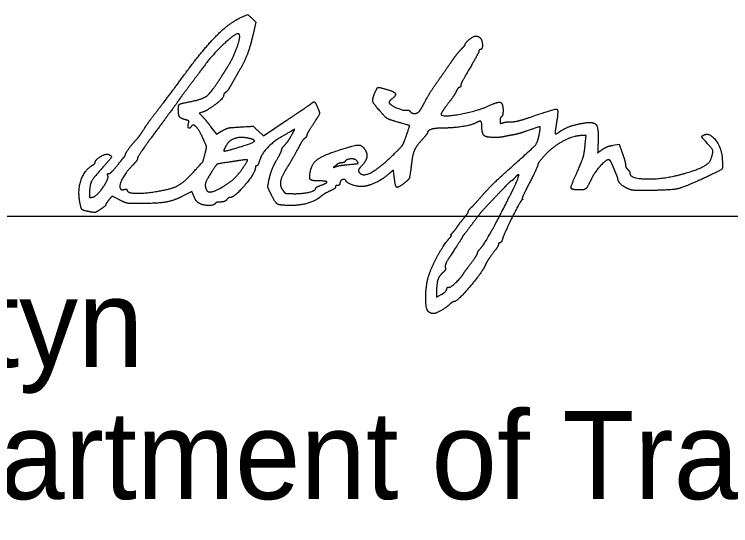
# Model space of a CAD drawing. Extents: x 0 to 34, y 0 to 22.
# Drawn here: x 25.627 to 26.765, y 7.199 to 8.012 of the extents above; entities that cross this region are included whole.
import ezdxf

# ---------------------------------------------------------------- set-up
doc = ezdxf.new("R2010")
doc.units = 0
doc.layers.add('SH_Data', color=7, linetype='Continuous')
doc.layers.add('SH_Text', color=7, linetype='Continuous')

msp = doc.modelspace()

# ---------------------------------------------------------------- linework, layer by layer
at = {"layer": 'SH_Data'}
msp.add_line((24.5, 7.691), (28, 7.691), dxfattribs=at)
at = {"layer": 'SH_Text'}
for points in [[(25.9853, 8.0062), (25.9979, 8.012), (26.0042, 8.0057), (26.0106, 7.9993), (26.0062, 7.9806)], [(25.9253, 7.8562), (25.9203, 7.8546), (25.9255, 7.8495)], [(25.9392, 7.8328), (25.9477, 7.8213), (25.9565, 7.8265)], [(26.0143, 7.8265), (26.0224, 7.8189), (26.0587, 7.843)], [(26.0682, 7.8212), (26.0726, 7.8292), (26.0671, 7.8263)], [(26.534, 7.8053), (26.5355, 7.8191), (26.5277, 7.8191)], [(26.5779, 7.8037), (26.5876, 7.8053), (26.5926, 7.7917)], [(26.23, 7.7576), (26.2293, 7.7644), (26.2234, 7.7593)], [(25.9123, 7.722), (25.909, 7.73), (25.8951, 7.7231)], [(25.7937, 7.7169), (25.7822, 7.7227), (25.7771, 7.7169)], [(26.2977, 7.5714), (26.2977, 7.5621), (26.3052, 7.5664)]]:
    msp.add_lwpolyline(points, dxfattribs=at)
for points in [[(25.8957, 7.9143), (25.9254, 7.9549), (25.9672, 7.9978), (25.9853, 8.0062)], [(25.9838, 7.9804), (25.9802, 7.984), (25.9416, 7.9483), (25.9262, 7.927)], [(25.9655, 7.9283), (25.9749, 7.9432), (25.9869, 7.9773), (25.9838, 7.9804)], [(26.0062, 7.9806), (26.0012, 7.9595), (25.992, 7.9359), (25.9826, 7.9199)], [(26.3433, 7.9643), (26.3433, 7.9671), (26.3565, 7.9774), (26.3602, 7.9775)], [(26.3602, 7.9775), (26.3623, 7.9775), (26.3652, 7.9762), (26.3668, 7.9747)], [(26.3668, 7.9747), (26.3703, 7.9712), (26.3707, 7.9559), (26.3673, 7.9559)], [(26.3367, 7.9562), (26.3403, 7.9598), (26.3433, 7.9634), (26.3433, 7.9643)], [(26.3229, 7.9389), (26.3269, 7.9448), (26.3331, 7.9525), (26.3367, 7.9562)], [(26.3649, 7.9534), (26.3649, 7.952), (26.3584, 7.9399), (26.3505, 7.9266)], [(26.3673, 7.9559), (26.366, 7.9559), (26.3649, 7.9548), (26.3649, 7.9534)], [(26.3013, 7.9079), (26.3092, 7.9192), (26.319, 7.9331), (26.3229, 7.9389)], [(25.9262, 7.927), (25.9226, 7.9221), (25.9132, 7.9094), (25.9053, 7.8989)], [(25.955, 7.9117), (25.9583, 7.9169), (25.963, 7.9244), (25.9655, 7.9283)], [(26.3505, 7.9266), (26.3426, 7.9132), (26.3361, 7.9008), (26.3361, 7.8991)], [(25.8555, 7.8609), (25.8644, 7.8722), (25.8825, 7.8963), (25.8957, 7.9143)], [(25.9052, 7.873), (25.9258, 7.8768), (25.9398, 7.8877), (25.955, 7.9117)], [(25.9826, 7.9199), (25.9791, 7.914), (25.9739, 7.9048), (25.971, 7.8995)], [(26.2799, 7.8743), (26.2837, 7.8816), (26.2933, 7.8967), (26.3013, 7.9079)], [(25.9053, 7.8989), (25.8974, 7.8884), (25.8893, 7.8774), (25.8873, 7.8745)], [(25.971, 7.8995), (25.9682, 7.8943), (25.9644, 7.8891), (25.9626, 7.888)], [(26.1992, 7.8862), (26.203, 7.8952), (26.2061, 7.8963), (26.2188, 7.8925)], [(26.2188, 7.8925), (26.2308, 7.889), (26.2337, 7.8828), (26.226, 7.8769)], [(26.3288, 7.8893), (26.3271, 7.8857), (26.3209, 7.8766), (26.3152, 7.8691)], [(26.3341, 7.8959), (26.333, 7.8959), (26.3306, 7.893), (26.3288, 7.8893)], [(26.3361, 7.8991), (26.3361, 7.8973), (26.3352, 7.8959), (26.3341, 7.8959)], [(25.9593, 7.8826), (25.9593, 7.8788), (25.9335, 7.8588), (25.9253, 7.8562)], [(25.9626, 7.888), (25.9608, 7.887), (25.9593, 7.8845), (25.9593, 7.8826)], [(26.209, 7.8568), (26.1975, 7.8698), (26.1953, 7.8766), (26.1992, 7.8862)], [(25.8873, 7.8745), (25.8853, 7.8715), (25.87, 7.8506), (25.8532, 7.8279)], [(25.8873, 7.8609), (25.8873, 7.8677), (25.8914, 7.8705), (25.9052, 7.873)], [(26.0587, 7.843), (26.0786, 7.8563), (26.0962, 7.8682), (26.0978, 7.8695)], [(26.0978, 7.8695), (26.1023, 7.8733), (26.1047, 7.8724), (26.1077, 7.8658)], [(26.226, 7.8769), (26.2233, 7.8749), (26.2218, 7.872), (26.2228, 7.8707)], [(26.2228, 7.8707), (26.2254, 7.8669), (26.2453, 7.8587), (26.25, 7.8595)], [(26.2706, 7.8581), (26.2719, 7.8598), (26.2761, 7.8671), (26.2799, 7.8743)], [(26.3152, 7.8691), (26.3096, 7.8617), (26.3049, 7.8544), (26.3049, 7.8531)], [(26.3049, 7.8531), (26.3049, 7.8478), (26.3645, 7.8587), (26.3825, 7.8673)], [(26.3825, 7.8673), (26.3955, 7.8735), (26.4033, 7.8703), (26.4033, 7.8589)], [(25.834, 7.8315), (25.837, 7.8363), (25.8467, 7.8495), (25.8555, 7.8609)], [(25.8983, 7.8445), (25.8911, 7.8463), (25.8873, 7.852), (25.8873, 7.8609)], [(26.1077, 7.8658), (26.1121, 7.8562), (26.1111, 7.8521), (26.1009, 7.8362)], [(26.2325, 7.8416), (26.2217, 7.8447), (26.2168, 7.8479), (26.209, 7.8568)], [(26.25, 7.8595), (26.2522, 7.8599), (26.2548, 7.859), (26.2556, 7.8577)], [(26.2556, 7.8577), (26.2578, 7.8542), (26.2678, 7.8545), (26.2706, 7.8581)], [(26.4033, 7.8589), (26.4033, 7.8544), (26.4022, 7.85), (26.4009, 7.8491)], [(26.4456, 7.8482), (26.486, 7.8621), (26.4919, 7.8605), (26.4878, 7.8366)], [(25.9034, 7.8382), (25.9043, 7.8418), (25.9031, 7.8433), (25.8983, 7.8445)], [(25.9255, 7.8495), (25.9283, 7.8467), (25.9345, 7.8392), (25.9392, 7.8328)], [(26.4009, 7.8491), (26.3996, 7.8483), (26.3985, 7.8455), (26.3985, 7.8428)], [(26.4168, 7.8412), (26.421, 7.841), (26.4339, 7.8442), (26.4456, 7.8482)], [(25.9077, 7.8335), (25.9052, 7.8296), (25.902, 7.8331), (25.9034, 7.8382)], [(25.9265, 7.8149), (25.9203, 7.8285), (25.9106, 7.8382), (25.9077, 7.8335)], [(25.9565, 7.8265), (25.963, 7.8304), (25.9706, 7.8321), (25.9857, 7.8329)], [(25.9857, 7.8329), (26.006, 7.8341), (26.0062, 7.8341), (26.0143, 7.8265)], [(26.1009, 7.8362), (26.0956, 7.8281), (26.0913, 7.8205), (26.0913, 7.8194)], [(26.2493, 7.8179), (26.255, 7.8347), (26.2546, 7.8353), (26.2325, 7.8416)], [(26.3583, 7.8385), (26.3527, 7.8355), (26.3225, 7.8311), (26.3075, 7.8311)], [(26.3697, 7.8338), (26.3697, 7.8411), (26.366, 7.8427), (26.3583, 7.8385)], [(26.389, 7.8162), (26.3766, 7.8162), (26.3697, 7.8225), (26.3697, 7.8338)], [(26.3985, 7.8428), (26.3985, 7.8389), (26.3995, 7.8383), (26.4039, 7.8397)], [(26.4039, 7.8397), (26.4069, 7.8407), (26.4127, 7.8413), (26.4168, 7.8412)], [(26.4609, 7.8216), (26.463, 7.8331), (26.4613, 7.8335), (26.4403, 7.8262)], [(26.4878, 7.8366), (26.4865, 7.829), (26.4857, 7.8224), (26.4862, 7.8219)], [(26.4938, 7.8257), (26.501, 7.8308), (26.5192, 7.8371), (26.5329, 7.8393)], [(26.5329, 7.8393), (26.5476, 7.8416), (26.5552, 7.8311), (26.5544, 7.8099)], [(25.8177, 7.8096), (25.8243, 7.8169), (25.8285, 7.8227), (25.834, 7.8315)], [(25.8532, 7.8279), (25.8364, 7.8053), (25.8226, 7.7851), (25.8225, 7.7831)], [(26.0671, 7.8263), (26.0437, 7.8137), (26.021, 7.793), (26.0168, 7.7806)], [(26.0554, 7.8031), (26.0608, 7.8091), (26.0633, 7.8127), (26.0682, 7.8212)], [(26.2833, 7.824), (26.2833, 7.8231), (26.2791, 7.8177), (26.2739, 7.8119)], [(26.3075, 7.8311), (26.296, 7.8311), (26.2833, 7.8274), (26.2833, 7.824)], [(26.4161, 7.7686), (26.4516, 7.8002), (26.4585, 7.8083), (26.4609, 7.8216)], [(26.4403, 7.8262), (26.4325, 7.8235), (26.4229, 7.8208), (26.4189, 7.8202)], [(26.4862, 7.8219), (26.4867, 7.8214), (26.4901, 7.8231), (26.4938, 7.8257)], [(26.7245, 7.8105), (26.7192, 7.8162), (26.719, 7.8189), (26.7236, 7.8206)], [(26.7236, 7.8206), (26.7322, 7.8239), (26.7506, 7.799), (26.7516, 7.7827)], [(25.8033, 7.7891), (25.8033, 7.7908), (25.8124, 7.8038), (25.8177, 7.8096)], [(25.9298, 7.7903), (25.9323, 7.8002), (25.932, 7.8024), (25.9265, 7.8149)], [(25.9975, 7.8152), (25.9866, 7.8174), (25.9693, 7.8123), (25.9649, 7.8057)], [(25.9869, 7.8017), (26.0061, 7.8076), (26.0101, 7.8127), (25.9975, 7.8152)], [(26.0877, 7.8144), (26.0858, 7.8128), (26.0827, 7.8086), (26.0809, 7.8051)], [(26.0913, 7.8194), (26.0913, 7.8182), (26.0897, 7.816), (26.0877, 7.8144)], [(26.231, 7.7906), (26.2414, 7.8006), (26.2455, 7.8068), (26.2493, 7.8179)], [(26.2739, 7.8119), (26.2655, 7.8024), (26.2597, 7.7899), (26.2581, 7.7771)], [(26.4057, 7.8176), (26.4024, 7.8168), (26.3949, 7.8162), (26.389, 7.8162)], [(26.4189, 7.8202), (26.4149, 7.8195), (26.409, 7.8184), (26.4057, 7.8176)], [(26.5277, 7.8191), (26.515, 7.8191), (26.4812, 7.8007), (26.4691, 7.7872)], [(26.5544, 7.8099), (26.5537, 7.7915), (26.5536, 7.7918), (26.5613, 7.7973)], [(26.7336, 7.7814), (26.7376, 7.7932), (26.736, 7.7981), (26.7245, 7.8105)], [(25.9649, 7.8057), (25.9579, 7.795), (25.9625, 7.7942), (25.9869, 7.8017)], [(26.0514, 7.7961), (26.0517, 7.7978), (26.0535, 7.801), (26.0554, 7.8031)], [(26.0809, 7.8051), (26.0727, 7.7897), (26.0649, 7.7759), (26.0588, 7.7662)], [(26.1347, 7.7934), (26.1665, 7.804), (26.1799, 7.8044), (26.185, 7.7949)], [(26.5194, 7.7575), (26.5284, 7.7774), (26.5324, 7.7906), (26.534, 7.8053)], [(26.5613, 7.7973), (26.5651, 7.8), (26.5726, 7.8029), (26.5779, 7.8037)], [(25.7553, 7.7771), (25.7554, 7.7809), (25.7721, 7.7908), (25.7759, 7.7894)], [(25.7759, 7.7894), (25.7819, 7.7871), (25.7796, 7.7822), (25.7653, 7.7663)], [(25.8009, 7.7848), (25.8022, 7.7864), (25.8033, 7.7884), (25.8033, 7.7891)], [(25.9101, 7.7598), (25.9262, 7.7774), (25.9265, 7.7779), (25.9298, 7.7903)], [(26.0429, 7.779), (26.0473, 7.7867), (26.0512, 7.7943), (26.0514, 7.7961)], [(26.0971, 7.7623), (26.0992, 7.7736), (26.1154, 7.787), (26.1347, 7.7934)], [(26.174, 7.7617), (26.1793, 7.7531), (26.2061, 7.7666), (26.231, 7.7906)], [(26.185, 7.7949), (26.1882, 7.7889), (26.1848, 7.7775), (26.1774, 7.7696)], [(26.4691, 7.7872), (26.4632, 7.7807), (26.4585, 7.7741), (26.4585, 7.7726)], [(26.5926, 7.7917), (26.5954, 7.7843), (26.5977, 7.7761), (26.5977, 7.7736)], [(25.7506, 7.7718), (25.7532, 7.7734), (25.7553, 7.7758), (25.7553, 7.7771)], [(25.7888, 7.7699), (25.7941, 7.7765), (25.7996, 7.7832), (25.8009, 7.7848)], [(25.8225, 7.7831), (25.8224, 7.7812), (25.8191, 7.7763), (25.8151, 7.7724)], [(25.9677, 7.7769), (25.9499, 7.7743), (25.9479, 7.7732), (25.9406, 7.762)], [(25.9851, 7.7796), (25.9795, 7.7787), (25.9717, 7.7775), (25.9677, 7.7769)], [(25.9901, 7.7679), (25.9979, 7.7793), (25.997, 7.7814), (25.9851, 7.7796)], [(26.0168, 7.7806), (26.0151, 7.7754), (26.0128, 7.7711), (26.0117, 7.7711)], [(26.032, 7.7512), (26.0336, 7.7589), (26.0385, 7.7714), (26.0429, 7.779)], [(26.1468, 7.7759), (26.1445, 7.7759), (26.1405, 7.7742), (26.138, 7.7721)], [(26.1523, 7.7781), (26.1516, 7.7769), (26.1491, 7.7759), (26.1468, 7.7759)], [(26.1708, 7.7792), (26.168, 7.7825), (26.1546, 7.7817), (26.1523, 7.7781)], [(26.1549, 7.7728), (26.1716, 7.7743), (26.174, 7.7753), (26.1708, 7.7792)], [(26.2581, 7.7771), (26.2553, 7.7546), (26.2536, 7.7492), (26.2479, 7.7447)], [(26.5709, 7.7807), (26.5666, 7.7807), (26.5483, 7.7602), (26.5436, 7.7501)], [(26.5765, 7.7741), (26.575, 7.7778), (26.5725, 7.7807), (26.5709, 7.7807)], [(26.6847, 7.7571), (26.7084, 7.7634), (26.7314, 7.7748), (26.7336, 7.7814)], [(26.7516, 7.7827), (26.7526, 7.7674), (26.7499, 7.7643), (26.7265, 7.7533)], [(25.7304, 7.7155), (25.7275, 7.734), (25.7382, 7.764), (25.7506, 7.7718)], [(25.7653, 7.7663), (25.7516, 7.7511), (25.7466, 7.741), (25.746, 7.7272)], [(25.7765, 7.7586), (25.7779, 7.7583), (25.7834, 7.7633), (25.7888, 7.7699)], [(25.8151, 7.7724), (25.8053, 7.7628), (25.7929, 7.7407), (25.7947, 7.736)], [(25.9602, 7.7392), (25.9714, 7.7462), (25.9824, 7.7567), (25.9901, 7.7679)], [(26.0097, 7.7681), (26.0095, 7.7596), (25.9764, 7.7207), (25.9693, 7.7207)], [(26.0117, 7.7711), (26.0106, 7.7711), (26.0097, 7.7698), (26.0097, 7.7681)], [(26.0588, 7.7662), (26.0508, 7.7536), (26.0486, 7.7384), (26.0537, 7.7316)], [(26.138, 7.7721), (26.1334, 7.7684), (26.1334, 7.7684), (26.1381, 7.77)], [(26.1381, 7.77), (26.1407, 7.771), (26.1483, 7.7722), (26.1549, 7.7728)], [(26.1774, 7.7696), (26.1746, 7.7667), (26.1731, 7.7631), (26.174, 7.7617)], [(26.372, 7.7259), (26.3792, 7.7343), (26.399, 7.7535), (26.4161, 7.7686)], [(26.4585, 7.7726), (26.4585, 7.771), (26.4525, 7.7581), (26.4453, 7.744)], [(26.5824, 7.76), (26.5806, 7.7641), (26.578, 7.7705), (26.5765, 7.7741)], [(26.5977, 7.7736), (26.5977, 7.7711), (26.5993, 7.7675), (26.6013, 7.7655)], [(26.6013, 7.7655), (26.6033, 7.7635), (26.6049, 7.7608), (26.6049, 7.7595)], [(25.7509, 7.7212), (25.7572, 7.7221), (25.7773, 7.7505), (25.7753, 7.7557)], [(25.7753, 7.7557), (25.7745, 7.7577), (25.7751, 7.759), (25.7765, 7.7586)], [(25.8536, 7.7305), (25.8763, 7.7342), (25.8959, 7.7444), (25.9101, 7.7598)], [(25.9406, 7.762), (25.9324, 7.7493), (25.9292, 7.7395), (25.9315, 7.7337)], [(26.1106, 7.7471), (26.0991, 7.7471), (26.0951, 7.7517), (26.0971, 7.7623)], [(26.2234, 7.7593), (26.214, 7.7511), (26.194, 7.7405), (26.1849, 7.7388)], [(26.2479, 7.7447), (26.2362, 7.7355), (26.2318, 7.7386), (26.23, 7.7576)], [(26.3694, 7.6421), (26.3771, 7.6508), (26.4303, 7.7545), (26.4282, 7.7566)], [(26.4225, 7.7525), (26.4201, 7.7496), (26.4175, 7.7471), (26.4167, 7.7471)], [(26.4282, 7.7566), (26.4275, 7.7573), (26.4249, 7.7555), (26.4225, 7.7525)], [(26.5267, 7.7327), (26.5122, 7.7327), (26.5106, 7.7382), (26.5194, 7.7575)], [(26.5858, 7.7504), (26.5857, 7.7515), (26.5842, 7.7558), (26.5824, 7.76)], [(26.6049, 7.7595), (26.6049, 7.7509), (26.6555, 7.7495), (26.6847, 7.7571)], [(26.7265, 7.7533), (26.6917, 7.737), (26.6707, 7.7322), (26.6313, 7.7318)], [(26.034, 7.7272), (26.0296, 7.7363), (26.0294, 7.7385), (26.032, 7.7512)], [(26.114, 7.7402), (26.1243, 7.7439), (26.1227, 7.7471), (26.1106, 7.7471)], [(26.1441, 7.7433), (26.1441, 7.7414), (26.1425, 7.7399), (26.1405, 7.7399)], [(26.1536, 7.7473), (26.1516, 7.7506), (26.1441, 7.7474), (26.1441, 7.7433)], [(26.1849, 7.7388), (26.1763, 7.7372), (26.1565, 7.7426), (26.1536, 7.7473)], [(26.4167, 7.7471), (26.416, 7.7471), (26.412, 7.7436), (26.4079, 7.7393)], [(26.4453, 7.744), (26.438, 7.7299), (26.4329, 7.7183), (26.4339, 7.7183)], [(26.5436, 7.7501), (26.5379, 7.7377), (26.5331, 7.7327), (26.5267, 7.7327)], [(26.6014, 7.7348), (26.5944, 7.7381), (26.5859, 7.7465), (26.5858, 7.7504)], [(25.7947, 7.736), (25.7956, 7.7336), (25.7979, 7.7327), (25.8009, 7.7334)], [(25.8009, 7.7334), (25.8035, 7.7341), (25.8057, 7.7338), (25.8057, 7.7327)], [(25.8057, 7.7327), (25.8057, 7.7281), (25.8313, 7.7269), (25.8536, 7.7305)], [(25.9315, 7.7337), (25.9335, 7.7284), (25.9471, 7.731), (25.9602, 7.7392)], [(26.0537, 7.7316), (26.0566, 7.7277), (26.0601, 7.7268), (26.0713, 7.7268)], [(26.0713, 7.7268), (26.0853, 7.7267), (26.1057, 7.7318), (26.1057, 7.7354)], [(26.1057, 7.7354), (26.1057, 7.7364), (26.1094, 7.7386), (26.114, 7.7402)], [(26.1315, 7.7326), (26.1242, 7.7293), (26.1165, 7.7247), (26.1123, 7.7212)], [(26.1369, 7.7375), (26.1369, 7.7361), (26.1345, 7.7339), (26.1315, 7.7326)], [(26.1405, 7.7399), (26.1385, 7.7399), (26.1369, 7.7388), (26.1369, 7.7375)], [(26.4079, 7.7393), (26.4038, 7.735), (26.3933, 7.724), (26.3845, 7.7147)], [(26.6313, 7.7318), (26.6164, 7.7316), (26.6061, 7.7326), (26.6014, 7.7348)], [(25.746, 7.7272), (25.7458, 7.7216), (25.7466, 7.7205), (25.7509, 7.7212)], [(25.8951, 7.7231), (25.8796, 7.7154), (25.8544, 7.7111), (25.8245, 7.7111)], [(25.9205, 7.7113), (25.9179, 7.7128), (25.9142, 7.7175), (25.9123, 7.722)], [(25.9693, 7.7207), (25.9681, 7.7207), (25.9657, 7.7191), (25.9641, 7.7171)], [(26.0658, 7.708), (26.0483, 7.7081), (26.0413, 7.7123), (26.034, 7.7272)], [(26.1123, 7.7212), (26.1046, 7.7149), (26.0803, 7.7079), (26.0658, 7.708)], [(26.3535, 7.7055), (26.3565, 7.7083), (26.3648, 7.7175), (26.372, 7.7259)], [(26.4339, 7.7183), (26.4349, 7.7183), (26.4345, 7.7175), (26.4331, 7.7165)], [(25.747, 7.6978), (25.7361, 7.6998), (25.7323, 7.7039), (25.7304, 7.7155)], [(25.7721, 7.7093), (25.7721, 7.7083), (25.7683, 7.705), (25.7637, 7.7019)], [(25.7771, 7.7169), (25.7744, 7.7137), (25.7721, 7.7103), (25.7721, 7.7093)], [(25.8245, 7.7111), (25.8089, 7.7111), (25.803, 7.7122), (25.7937, 7.7169)], [(25.9461, 7.7111), (25.9441, 7.7079), (25.9266, 7.7081), (25.9205, 7.7113)], [(25.9543, 7.7135), (25.9506, 7.7135), (25.9469, 7.7125), (25.9461, 7.7111)], [(25.9641, 7.7171), (25.9625, 7.7152), (25.9581, 7.7135), (25.9543, 7.7135)], [(26.3845, 7.7147), (26.3757, 7.7054), (26.3658, 7.6942), (26.3625, 7.6897)], [(26.4331, 7.7165), (26.4304, 7.7147), (26.4052, 7.6637), (26.4022, 7.6541)], [(25.7637, 7.7019), (25.7572, 7.6974), (25.7536, 7.6965), (25.747, 7.6978)], [(26.3415, 7.6884), (26.3451, 7.6927), (26.3481, 7.6971), (26.3481, 7.6983)], [(26.3481, 7.6983), (26.3482, 7.6994), (26.3506, 7.7027), (26.3535, 7.7055)], [(26.3313, 7.6751), (26.3333, 7.6782), (26.3379, 7.6842), (26.3415, 7.6884)], [(26.3625, 7.6897), (26.3544, 7.6788), (26.3439, 7.665), (26.3409, 7.6614)], [(26.3235, 7.6651), (26.3258, 7.6676), (26.3293, 7.6721), (26.3313, 7.6751)], [(26.3209, 7.6607), (26.32, 7.6607), (26.3212, 7.6627), (26.3235, 7.6651)], [(26.3409, 7.6614), (26.3396, 7.6598), (26.3385, 7.6581), (26.3385, 7.6576)], [(26.2875, 7.6027), (26.2934, 7.6176), (26.3105, 7.6475), (26.3176, 7.6553)], [(26.3176, 7.6553), (26.3203, 7.6583), (26.3218, 7.6607), (26.3209, 7.6607)], [(26.3385, 7.6576), (26.3385, 7.657), (26.3322, 7.6471), (26.3244, 7.6354)], [(26.4022, 7.6541), (26.4013, 7.6512), (26.3996, 7.6487), (26.3983, 7.6487)], [(26.3625, 7.6318), (26.3625, 7.6331), (26.3656, 7.6377), (26.3694, 7.6421)], [(26.3961, 7.6462), (26.3961, 7.6449), (26.3918, 7.6381), (26.3866, 7.6312)], [(26.3983, 7.6487), (26.3971, 7.6487), (26.3961, 7.6476), (26.3961, 7.6462)], [(26.3244, 7.6354), (26.3158, 7.6224), (26.3108, 7.6126), (26.3115, 7.6099)], [(26.3523, 7.6159), (26.3579, 7.6233), (26.3625, 7.6304), (26.3625, 7.6318)], [(26.3866, 7.6312), (26.3814, 7.6243), (26.3763, 7.6163), (26.3752, 7.6135)], [(26.3397, 7.5987), (26.341, 7.6008), (26.3467, 7.6086), (26.3523, 7.6159)], [(26.3115, 7.6099), (26.3122, 7.6074), (26.3106, 7.6038), (26.3078, 7.6013)], [(26.3752, 7.6135), (26.3716, 7.6036), (26.3304, 7.5551), (26.3257, 7.5551)], [(26.2857, 7.5383), (26.2798, 7.5421), (26.281, 7.5864), (26.2875, 7.6027)], [(26.3078, 7.6013), (26.3019, 7.5961), (26.2977, 7.5838), (26.2977, 7.5714)], [(26.3169, 7.5779), (26.3188, 7.5768), (26.3355, 7.5919), (26.3397, 7.5987)], [(26.3052, 7.5664), (26.3094, 7.5688), (26.3133, 7.5726), (26.3139, 7.5749)], [(26.3139, 7.5749), (26.3145, 7.5772), (26.3159, 7.5786), (26.3169, 7.5779)], [(26.3183, 7.5506), (26.3121, 7.5449), (26.2961, 7.5359), (26.2922, 7.536)], [(26.3257, 7.5551), (26.3243, 7.5551), (26.321, 7.5531), (26.3183, 7.5506)], [(26.2922, 7.536), (26.2906, 7.536), (26.2877, 7.537), (26.2857, 7.5383)]]:
    msp.add_open_spline(points, degree=2, dxfattribs=at)

# ---------------------------------------------------------------- texts
for s, p in [('Pamela Boratyn', (24.5, 7.451)), ('Director, Department of Transportation', (24.5, 7.241))]:
    msp.add_text(s, height=0.14, dxfattribs=at).set_placement(p)

doc.saveas('drawing.dxf')
